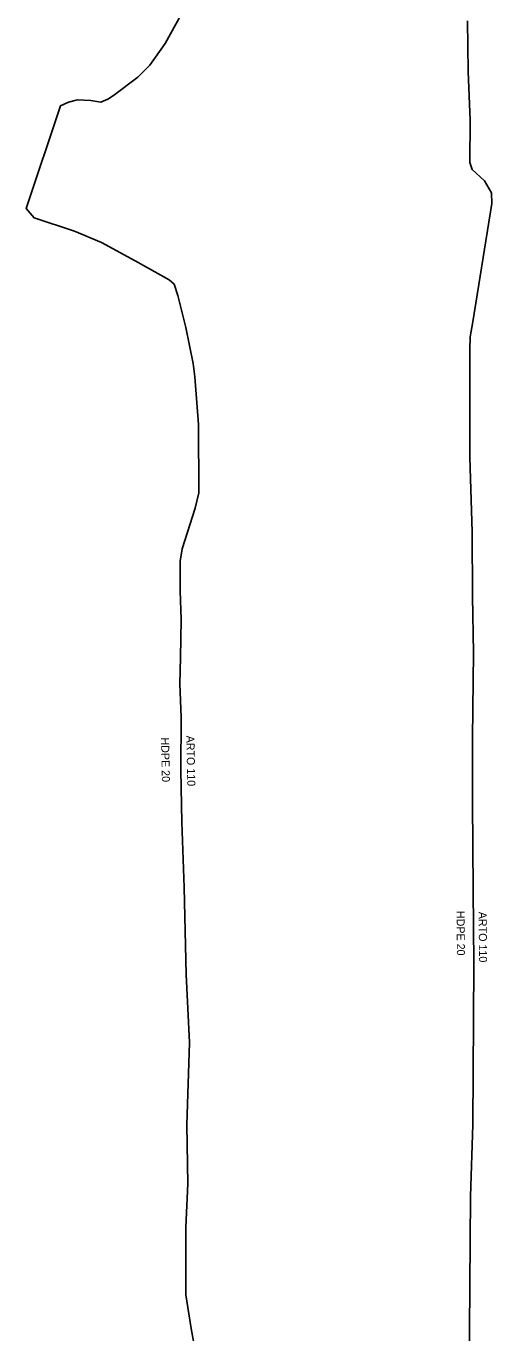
# Model space of a CAD drawing. Extents: x -651943 to -618711, y -1138561 to -1100552.
# Drawn here: x -640532.9 to -640489.2, y -1115429.4 to -1115307 of the extents above; entities that cross this region are included whole.
import ezdxf

# ---------------------------------------------------------------- set-up
doc = ezdxf.new("R2010")
doc.units = 0
for name, color, linetype in [('KT optika', 7, 'Continuous'), ('KT trasa', 7, 'Continuous'), ('KT zařízení', 7, 'Continuous')]:
    doc.layers.add(name, color=color, linetype=linetype)

msp = doc.modelspace()

# ---------------------------------------------------------------- linework, layer by layer
at = {"layer": 'KT optika'}
for points in [[(-640518.34, -1115371.74), (-640518.46, -1115368.62), (-640518.39, -1115366.14), (-640518.33, -1115362.58), (-640518.42, -1115359.89), (-640518.44, -1115357.12), (-640518.24, -1115355.96), (-640517.02, -1115352.15), (-640516.68, -1115350.71), (-640516.72, -1115344.31), (-640517.06, -1115339.84), (-640517.2, -1115338.6), (-640517.91, -1115335.24), (-640518.64, -1115332.22), (-640519, -1115331.17), (-640519.45, -1115330.76), (-640522.64, -1115328.99), (-640525.8, -1115327.25), (-640528.34, -1115326.2), (-640532.11, -1115324.94), (-640532.86, -1115324.09), (-640529.65, -1115314.46), (-640528.89, -1115314.1), (-640528.05, -1115313.9), (-640526.8, -1115313.95), (-640525.87, -1115314.1), (-640525.19, -1115313.84), (-640524.68, -1115313.5), (-640522.39, -1115311.78), (-640521.26, -1115310.64), (-640519.83, -1115308.62), (-640517.33, -1115304.06)], [(-640491.49, -1115306.48), (-640491.43, -1115311.25), (-640491.26, -1115315.8), (-640491.3, -1115319.77), (-640491.08, -1115320.43), (-640489.91, -1115321.48), (-640489.25, -1115322.62), (-640489.22, -1115323.6), (-640490.99, -1115334.68), (-640491.26, -1115336.09), (-640491.28, -1115337.33), (-640491.28, -1115340.48), (-640491.3, -1115347.37), (-640491.08, -1115354.39), (-640491.05, -1115360.41), (-640490.95, -1115365.7), (-640491.03, -1115373.68), (-640491.05, -1115379.73), (-640490.98, -1115387.91), (-640490.92, -1115394.81), (-640490.93, -1115400.1), (-640491.01, -1115409.9), (-640491.22, -1115416.65), (-640491.31, -1115429.18), (-640491.3, -1115443.58)], [(-640517.89, -1115423.16), (-640517.89, -1115419.53), (-640517.7, -1115415.45), (-640517.79, -1115409.93), (-640517.54, -1115402.21), (-640517.86, -1115395.83), (-640518.04, -1115387.7), (-640518.27, -1115381.58), (-640518.37, -1115376.72), (-640518.34, -1115371.74)], [(-640517.41, -1115429.01), (-640517.9, -1115425.86), (-640517.89, -1115423.16)], [(-640516.97, -1115431.41), (-640517.41, -1115429.01)]]:
    msp.add_lwpolyline(points, dxfattribs=at)
at = {"layer": 'KT trasa'}
for points in [[(-640518.34, -1115371.74), (-640518.46, -1115368.62), (-640518.39, -1115366.14), (-640518.33, -1115362.58), (-640518.42, -1115359.89), (-640518.44, -1115357.12), (-640518.24, -1115355.96), (-640517.02, -1115352.15), (-640516.68, -1115350.71), (-640516.72, -1115344.31), (-640517.06, -1115339.84), (-640517.2, -1115338.6), (-640517.91, -1115335.24), (-640518.64, -1115332.22), (-640519, -1115331.17), (-640519.45, -1115330.76), (-640522.64, -1115328.99), (-640525.8, -1115327.25), (-640528.34, -1115326.2), (-640532.11, -1115324.94), (-640532.86, -1115324.09), (-640529.65, -1115314.46), (-640528.89, -1115314.1), (-640528.05, -1115313.9), (-640526.8, -1115313.95), (-640525.87, -1115314.1), (-640525.19, -1115313.84), (-640524.68, -1115313.5), (-640522.39, -1115311.78), (-640521.26, -1115310.64), (-640519.83, -1115308.62), (-640517.33, -1115304.06)], [(-640491.49, -1115306.48), (-640491.43, -1115311.25), (-640491.26, -1115315.8), (-640491.3, -1115319.77), (-640491.08, -1115320.43), (-640489.91, -1115321.48), (-640489.25, -1115322.62), (-640489.22, -1115323.6), (-640490.99, -1115334.68), (-640491.26, -1115336.09), (-640491.28, -1115337.33), (-640491.28, -1115340.48), (-640491.3, -1115347.37), (-640491.08, -1115354.39), (-640491.05, -1115360.41), (-640490.95, -1115365.7), (-640491.03, -1115373.68), (-640491.05, -1115379.73), (-640490.98, -1115387.91), (-640490.92, -1115394.81), (-640490.93, -1115400.1), (-640491.01, -1115409.9), (-640491.22, -1115416.65), (-640491.31, -1115429.18), (-640491.3, -1115443.58)], [(-640517.89, -1115423.16), (-640517.89, -1115419.53), (-640517.7, -1115415.45), (-640517.79, -1115409.93), (-640517.54, -1115402.21), (-640517.86, -1115395.83), (-640518.04, -1115387.7), (-640518.27, -1115381.58), (-640518.37, -1115376.72), (-640518.34, -1115371.74)], [(-640517.41, -1115429.01), (-640517.9, -1115425.86), (-640517.89, -1115423.16)], [(-640516.97, -1115431.41), (-640517.41, -1115429.01)]]:
    msp.add_lwpolyline(points, dxfattribs=at)
at = {"layer": 'KT zařízení'}
for points in [[(-640518.34, -1115371.74), (-640518.46, -1115368.62), (-640518.39, -1115366.14), (-640518.33, -1115362.58), (-640518.42, -1115359.89), (-640518.44, -1115357.12), (-640518.24, -1115355.96), (-640517.02, -1115352.15), (-640516.68, -1115350.71), (-640516.72, -1115344.31), (-640517.06, -1115339.84), (-640517.2, -1115338.6), (-640517.91, -1115335.24), (-640518.64, -1115332.22), (-640519, -1115331.17), (-640519.45, -1115330.76), (-640522.64, -1115328.99), (-640525.8, -1115327.25), (-640528.34, -1115326.2), (-640532.11, -1115324.94), (-640532.86, -1115324.09), (-640529.65, -1115314.46), (-640528.89, -1115314.1), (-640528.05, -1115313.9), (-640526.8, -1115313.95), (-640525.87, -1115314.1), (-640525.19, -1115313.84), (-640524.68, -1115313.5), (-640522.39, -1115311.78), (-640521.26, -1115310.64), (-640519.83, -1115308.62), (-640517.33, -1115304.06)], [(-640491.49, -1115306.48), (-640491.43, -1115311.25), (-640491.26, -1115315.8), (-640491.3, -1115319.77), (-640491.08, -1115320.43), (-640489.91, -1115321.48), (-640489.25, -1115322.62), (-640489.22, -1115323.6), (-640490.99, -1115334.68), (-640491.26, -1115336.09), (-640491.28, -1115337.33), (-640491.28, -1115340.48), (-640491.3, -1115347.37), (-640491.08, -1115354.39), (-640491.05, -1115360.41), (-640490.95, -1115365.7), (-640491.03, -1115373.68), (-640491.05, -1115379.73), (-640490.98, -1115387.91), (-640490.92, -1115394.81), (-640490.93, -1115400.1), (-640491.01, -1115409.9), (-640491.22, -1115416.65), (-640491.31, -1115429.18), (-640491.3, -1115443.58)], [(-640517.89, -1115423.16), (-640517.89, -1115419.53), (-640517.7, -1115415.45), (-640517.79, -1115409.93), (-640517.54, -1115402.21), (-640517.86, -1115395.83), (-640518.04, -1115387.7), (-640518.27, -1115381.58), (-640518.37, -1115376.72), (-640518.34, -1115371.74)], [(-640517.41, -1115429.01), (-640517.9, -1115425.86), (-640517.89, -1115423.16)], [(-640516.97, -1115431.41), (-640517.41, -1115429.01)]]:
    msp.add_lwpolyline(points, dxfattribs=at)

# ---------------------------------------------------------------- texts
for s, rotation, p in [('HDPE 20', 271.1788, (-640520.22, -1115373.64)), ('ARTO 110', 271.1788, (-640517.85, -1115373.47)), ('HDPE 20', 270.4982, (-640492.53, -1115389.89)), ('ARTO 110', 270.4982, (-640490.46, -1115389.97))]:
    msp.add_text(s, height=0.75, rotation=rotation, dxfattribs=at).set_placement(p)

doc.saveas('drawing.dxf')
